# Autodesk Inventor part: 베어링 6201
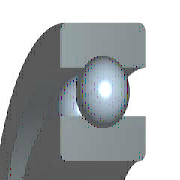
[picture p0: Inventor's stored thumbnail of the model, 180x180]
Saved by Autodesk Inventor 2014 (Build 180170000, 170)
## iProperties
Created: 2009-02
Part Number: 베어링 6201
Material: 강, 연강
Description: 깊은 그루브 볼 베어링
Document SubType Name: Modeling
Standard: KS B 2023
Designer: KYOUNG IL JANG
Standards Organization: KS
Language: ko-KR
Size Designation: 6201 - 12 x 32 x 10
Categories: <MemberInstance><Categories><Category DisplayName="샤프트 부품" InternalName="7f7aeb1f-a693-4053-b835-cee3144e0d98" Mnemonic="SHFT"><Category DisplayName="베어링" Inter
Density: 7.86 g/cm^3
Mass: 36.8026 g
Surface Area: 42.5728 cm^2
Volume: 4.68226 cm^3
Vendor: CBT Solutions
Appearance: 강철
Company: 한국ATC센터
IsCustomPart: 1
Author: KYOUNG IL JANG
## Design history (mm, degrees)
sketch "스케치" dims "d0" = 5.2 (= -0.26 x WD + 0.26 x BD)
  geometry: L1 (2.4, 11)-(7.6, 11); L2 (5, 11)-(5, 8.4); L3 (5, 11)-(5, 13.6); L4 (3.068, 9.26)-(0, 9.26); L5 (0, 6)-(10, 6); L6 (3.068, 12.74)-(0, 12.74); L7 (0, 16)-(10, 16); L8 (10, 6)-(10, 9.26); L9 (6.932, 9.26)-(10, 9.26); L10 (6.932, 12.74)-(10, 12.74); L11 (10, 16)-(10, 12.74); L12 (-1.4, 0)-(8.4, 0) reference; L13 (0, -0.3)-(0, 5.3) reference
  constraints: 22 end point, 4 point on line, 2 collinear, 2 perpendicular, 2 symmetric about line, 1 midpoint, 1 parallel, 14 other
  dimensions: "d9" = 12 diameter of L5 L12 (= WD); "d11" = 32 diameter of L7 L12 (= BD); "d12" = 10 distance between parallel lines of L8 L13 (= KB); "d13" = 18.52 diameter of L9 L12 (= 0.326 x BD + 0.674 x WD)
revolve "본체" stored, may be unused: angle "d6" = 90 deg
revolve "볼" stored, may be unused: angle "d7" = 90 deg
pattern_circular "IDS_ARRAYBALL[SIMPL:T]" dims angle "d3" = 360 deg
body "Solid1"
fillet "모깎기1" dims "d1" = 0.6 (= KRS)
other parameters: "WD" = 12 [user parameter; used in 5 equation terms], "BD" = 32 [user parameter; used in 5 equation terms], "KB" = 10 [user parameter; used in 1 equation term], "KRS" = 0.6 [user parameter; used in 1 equation term], "d4" = 0, "d5" = 0, "d8" = 0, "d14" = 0, "d15" = 0, "BBA" = 0 [user parameter], "BC0" = 3100000 [user parameter], "BC" = 6890000 [user parameter], "BR" = 16 (= 0.5 x BD) [user parameter], "WR" = 6 (= 0.5 x WD) [user parameter]
